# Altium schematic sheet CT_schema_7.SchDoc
size 287 x 160 mm
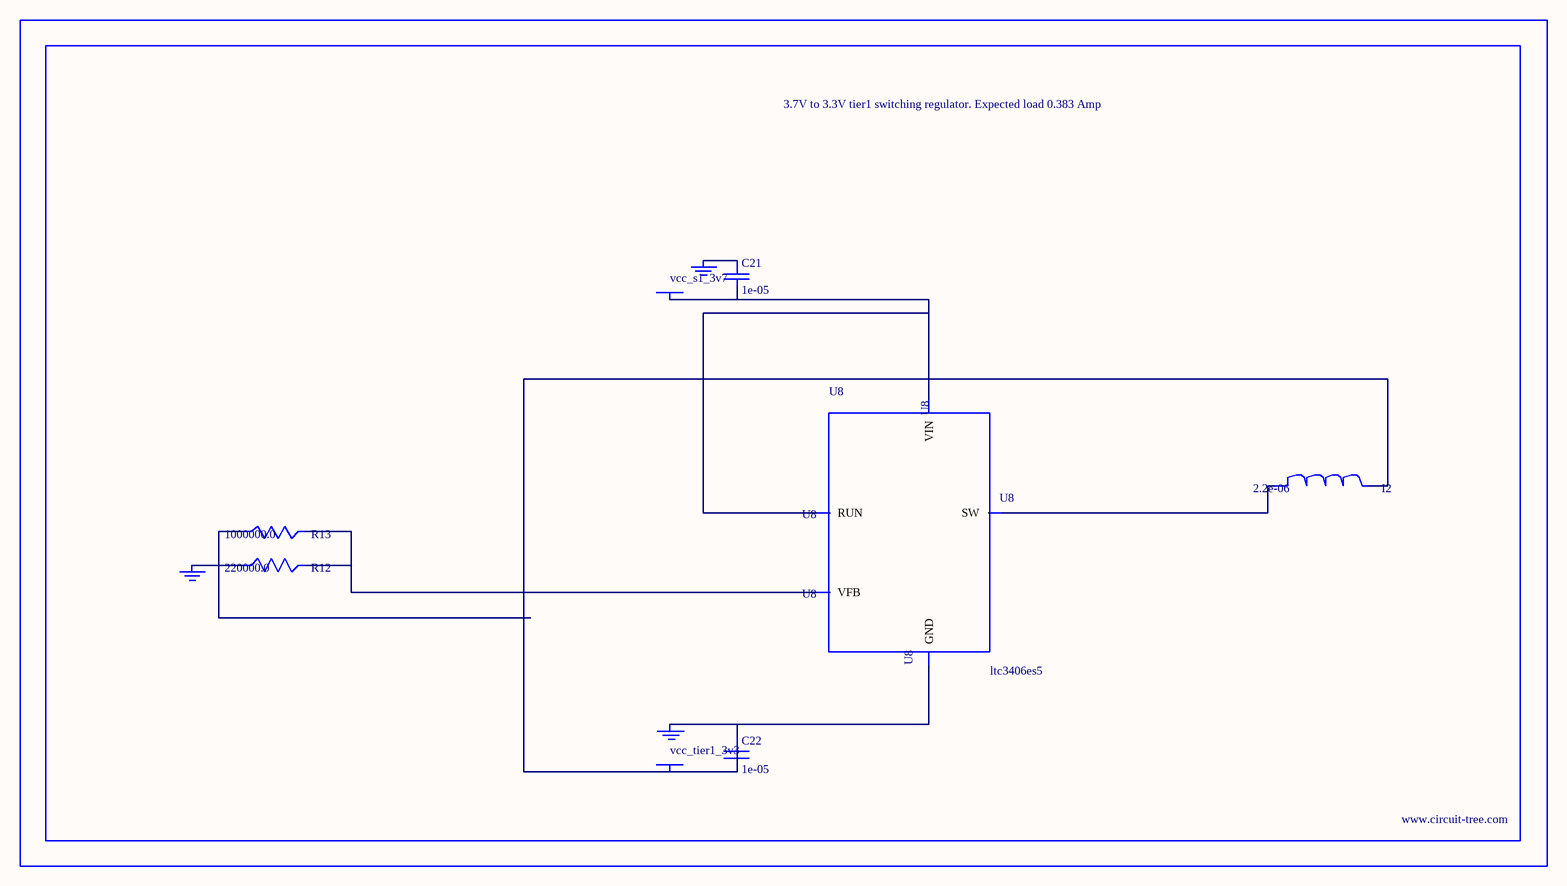
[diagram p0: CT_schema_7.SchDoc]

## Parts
BORDER6  (no value)
C21  1e-05  [C0805]
C22  1e-05  [C0805]
GND_INSTANCE_6_0  (no value)
GND_INSTANCE_6_1  (no value)
GND_INSTANCE_6_2  (no value)
I2  2.2e-06  [L0805]
POWER_INSTANCE_6_0  vcc_tier1_3v3
POWER_INSTANCE_6_1  vcc_s1_3v7
R12  220000.0  [R0603]
R13  1000000.0  [R0603]
U8  ltc3406es5  [TSOT-23-5]

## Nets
NetC21_1: C21.1 GND_INSTANCE_6_1.0(GND)
NetC21_2: C21.2 POWER_INSTANCE_6_1.0(PWR) U8.1(RUN) U8.4(VIN)
NetC22_1: C22.1 GND_INSTANCE_6_0.0(GND) U8.2(GND)
NetC22_2: C22.2 I2.2 POWER_INSTANCE_6_0.0(PWR) R13.1
NetGND_INSTANCE_6_2_0: GND_INSTANCE_6_2.0(GND) R12.1
NetI2_1: I2.1 U8.3(SW)
NetR12_2: R12.2 R13.2 U8.5(VFB)

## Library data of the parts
BORDER6 = BORDER_PAGE6
C21 C22 = C0805C106K8RACTU
GND_INSTANCE_6_0-GND_INSTANCE_6_2 = GND
I2 = L0805C2R2MDWIT
POWER_INSTANCE_6_0 POWER_INSTANCE_6_1 = PWR
R12 = RC0603JR-07220KL
R13 = RC0603JR-071ML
